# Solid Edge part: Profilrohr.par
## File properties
Username: ahadarics
Dokumentum tartalom típus: 0
Author: ahadarics
Last saved by: ahadarics
Revision: 82
Sűrűség: 0,000 kg/m^3
Pontosság: 0,990
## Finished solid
Body 1: solid body, 6 faces, 6 edges, 0 vertices.
  Faces by surface: cone 2, cylinder 2, plane 2
  Edges by curve: circle 6
Bounding box of the edges (mm): 21.270 x 21.270 x 192.000, from (-10.635, -10.635, -171) to (10.635, 10.635, 21).
Cylindrical faces by radius (mm): R10 x1, R10.635 x1
Conical faces (half-angle, radius in mm at the cone's reference point): 15 deg R10.067 x2
Planar faces by outward normal: +z 1, -z 1
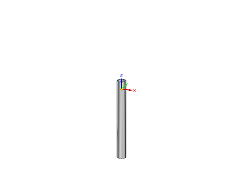
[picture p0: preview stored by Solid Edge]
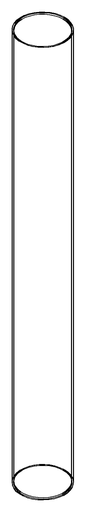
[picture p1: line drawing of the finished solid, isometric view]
